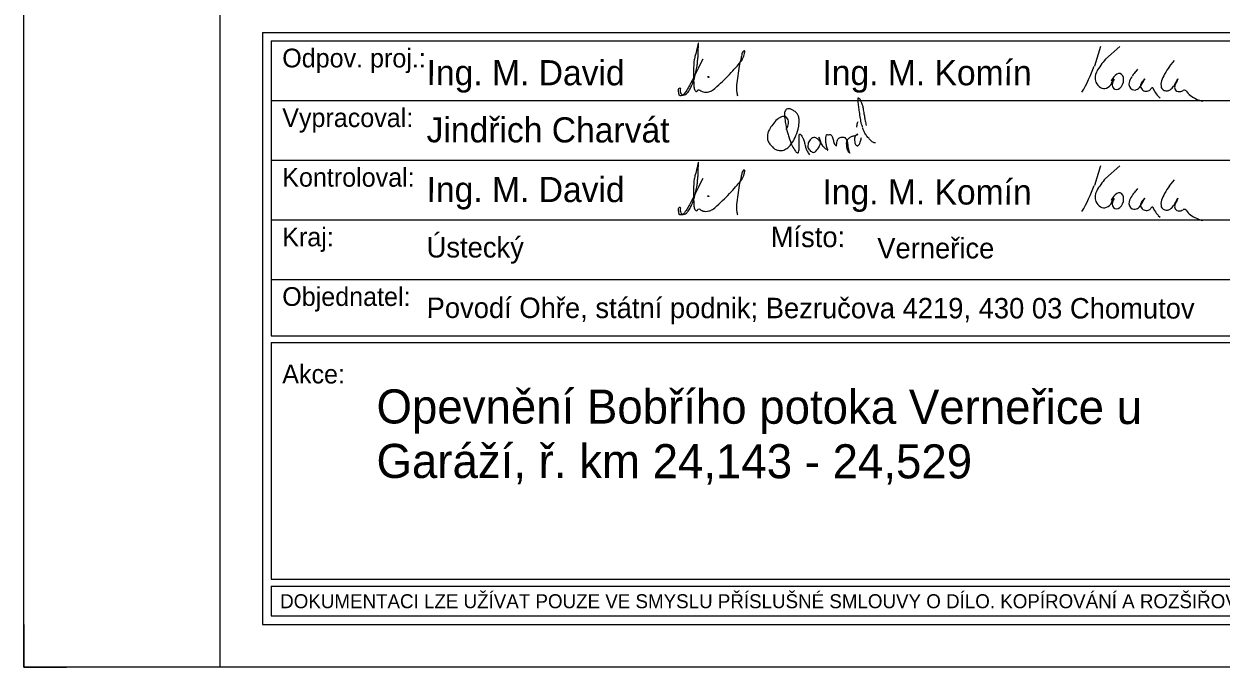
# Model space of a CAD drawing. Extents: x 67.3 to 115.4, y -93.9 to -78.3.
# Drawn here: x 67.26 to 74.28, y -93.93 to -90.16 of the extents above; entities that cross this region are included whole.
import ezdxf

# ---------------------------------------------------------------- set-up
doc = ezdxf.new("R2010")
doc.units = 0
for name, color, linetype in [('07_rozpiska', 7, 'Continuous'), ('07_rámeček', 7, 'Continuous'), ('Default', 7, 'Continuous'), ('Rozpiska + rámeček', 7, 'Continuous')]:
    doc.layers.add(name, color=color, linetype=linetype)

# ---------------------------------------------------------------- blocks, each defined once
blk = doc.blocks.new('Charvat')
at = {"layer": 'Rozpiska + rámeček'}
for points in [[(0.0826, 0.02), (0.0817, 0.0228), (0.0806, 0.0281), (0.0796, 0.0345), (0.0789, 0.0395), (0.0784, 0.0445), (0.0784, 0.0456), (0.0785, 0.0469), (0.0787, 0.0476), (0.0791, 0.0473), (0.0804, 0.0456), (0.0816, 0.0427), (0.0827, 0.0394), (0.0832, 0.0363), (0.0841, 0.0314), (0.0846, 0.0282), (0.0855, 0.0238), (0.086, 0.0216)], [(0.0108, 0.0178), (0.0123, 0.0208), (0.0129, 0.0234), (0.0122, 0.0279), (0.0108, 0.0294), (0.0087, 0.0301), (0.0059, 0.0293), (0.0024, 0.0271), (-0.0017, 0.0225), (-0.0049, 0.0177), (-0.0062, 0.0145), (-0.0067, 0.0115), (-0.0063, 0.0075), (-0.0059, 0.0064), (-0.0039, 0.0034), (-0.0014, 0.0007), (0.001, -0.001), (0.0043, -0.0019), (0.0075, -0.0019), (0.0097, -0.001), (0.0131, 0.0013), (0.0158, 0.0045), (0.0192, 0.0101), (0.022, 0.0182), (0.0223, 0.0193), (0.023, 0.0256), (0.0227, 0.0293), (0.0219, 0.0315), (0.0199, 0.034), (0.017, 0.036), (0.0147, 0.0371), (0.0142, 0.0372), (0.013, 0.0373), (0.0113, 0.0368), (0.0106, 0.0362), (0.0097, 0.0348), (0.0095, 0.0343), (0.0093, 0.0333), (0.0093, 0.0314), (0.0096, 0.0279), (0.0105, 0.0221), (0.012, 0.0151), (0.0133, 0.0108), (0.0166, 0.0023), (0.0195, -0.0026), (0.0202, -0.0035), (0.0214, -0.0042), (0.022, -0.0042), (0.0225, -0.0034), (0.023, -0.0014), (0.0231, 0), (0.0231, 0.0051), (0.0231, 0.0111), (0.0231, 0.0124), (0.0233, 0.0132), (0.0236, 0.0135), (0.024, 0.0133), (0.0254, 0.0115), (0.0268, 0.0092), (0.0279, 0.0059), (0.0289, 0.0018), (0.0298, -0.0012), (0.0315, -0.0041), (0.0327, -0.0059)], [(0.0771, 0.0198), (0.0779, 0.024), (0.0784, 0.0252)], [(0.0428, 0.0062), (0.0417, 0.0075), (0.0401, 0.009), (0.0394, 0.0095), (0.0378, 0.0101), (0.0368, 0.0101), (0.0353, 0.0098), (0.034, 0.0088), (0.0326, 0.0071), (0.0316, 0.0051), (0.0313, 0.0026), (0.0313, 0.0011), (0.0322, -0.0007), (0.0338, -0.0025), (0.0354, -0.0034), (0.0366, -0.0037), (0.0381, -0.0031), (0.0397, -0.0014), (0.0411, 0.0004), (0.0422, 0.0025), (0.043, 0.005), (0.043, 0.0063), (0.0429, 0.0069), (0.0424, 0.0086), (0.0414, 0.0106), (0.0421, 0.009), (0.0433, 0.0053), (0.0444, 0.0034), (0.0458, 0.0017), (0.0476, 0), (0.0497, -0.0015), (0.0498, -0.0016), (0.0499, -0.0016), (0.0499, -0.0014), (0.0492, 0.0003), (0.0487, 0.0022), (0.0482, 0.0055), (0.048, 0.0086), (0.0484, 0.0114), (0.0491, 0.0131), (0.0493, 0.013), (0.0506, 0.0127), (0.0522, 0.0131), (0.0539, 0.0111), (0.0547, 0.0094), (0.0552, 0.0074), (0.0556, 0.0056), (0.0566, 0.0038), (0.058, 0.0025), (0.0582, 0.0031), (0.0585, 0.0057), (0.0589, 0.0076), (0.0593, 0.0083), (0.0604, 0.0095), (0.0616, 0.0102), (0.0632, 0.0106), (0.065, 0.0106), (0.0665, 0.0094), (0.0678, 0.0078), (0.0686, 0.0033), (0.0691, 0.0001), (0.0701, -0.0031), (0.0705, -0.0044), (0.0697, -0.0035), (0.0682, -0.0005), (0.0677, 0.0025), (0.0677, 0.0059), (0.0683, 0.0079), (0.0702, 0.01), (0.0728, 0.0114), (0.0756, 0.0122), (0.0781, 0.0133), (0.0764, 0.0125), (0.0755, 0.0112), (0.0751, 0.0096), (0.0751, 0.0075), (0.0753, 0.005), (0.0753, 0.0048), (0.0758, 0.0038), (0.0766, 0.003), (0.0772, 0.0026), (0.0776, 0.0025), (0.0783, 0.0027), (0.0791, 0.0034), (0.0799, 0.0047), (0.0806, 0.0069), (0.0816, 0.0104)], [(0.0947, 0.0053), (0.0934, 0.0053), (0.0921, 0.0059), (0.0901, 0.0076), (0.0883, 0.0095), (0.0858, 0.0127), (0.0839, 0.0159), (0.0829, 0.0186), (0.0827, 0.0193)]]:
    blk.add_spline(points, degree=3, dxfattribs=at)

msp = doc.modelspace()

# ---------------------------------------------------------------- linework, layer by layer
at = {"layer": '07_rozpiska'}
for points in [[(71.2105, -90.2979), (71.2118, -90.2881), (71.2111, -90.2684), (71.2033, -90.2992), (71.193, -90.3413), (71.1868, -90.3675), (71.1836, -90.4112), (71.182, -90.4469), (71.1852, -90.5214), (71.1884, -90.5411), (71.2011, -90.5528), (71.2056, -90.5496), (71.2066, -90.5473), (71.2137, -90.5424), (71.2263, -90.5489), (71.24, -90.5544), (71.2549, -90.557), (71.273, -90.5541), (71.2934, -90.5457), (71.32, -90.5243), (71.3637, -90.4832), (71.4039, -90.442), (71.4379, -90.4035), (71.4654, -90.3701), (71.4803, -90.3371), (71.4839, -90.3209), (71.4826, -90.3141), (71.4764, -90.3154), (71.4657, -90.3387), (71.4599, -90.3626), (71.4512, -90.4044), (71.4424, -90.4601), (71.4353, -90.5162), (71.4346, -90.545), (71.4382, -90.5667), (71.4401, -90.5774)], [(71.2043, -90.4031), (71.2063, -90.3772), (71.2088, -90.3546), (71.2108, -90.3303), (71.2105, -90.2979)], [(71.2367, -90.3636), (71.2092, -90.4184), (71.1629, -90.5104), (71.1295, -90.5648), (71.1172, -90.5761), (71.1078, -90.5777), (71.102, -90.5771), (71.0977, -90.5703), (71.0958, -90.5583)], [(71.0958, -90.5583), (71.0939, -90.5466), (71.0948, -90.5389), (71.0997, -90.5324), (71.1033, -90.5317), (71.1052, -90.5437), (71.1058, -90.558), (71.1139, -90.5703), (71.1253, -90.5745), (71.136, -90.5706), (71.1454, -90.5628), (71.1505, -90.556), (71.1658, -90.5317), (71.1719, -90.5201), (71.1878, -90.4738), (71.2043, -90.4031)], [(71.2691, -90.4653), (71.2668, -90.4663), (71.2668, -90.4683), (71.2685, -90.4692), (71.2717, -90.4699), (71.2723, -90.4683), (71.2723, -90.4666), (71.2691, -90.4653)], [(71.2105, -90.9979), (71.2118, -90.9881), (71.2111, -90.9684), (71.2033, -90.9992), (71.193, -91.0413), (71.1868, -91.0675), (71.1836, -91.1112), (71.182, -91.1469), (71.1852, -91.2214), (71.1884, -91.2411), (71.2011, -91.2528), (71.2056, -91.2496), (71.2066, -91.2473), (71.2137, -91.2424), (71.2263, -91.2489), (71.24, -91.2544), (71.2549, -91.257), (71.273, -91.2541), (71.2934, -91.2457), (71.32, -91.2243), (71.3637, -91.1832), (71.4039, -91.142), (71.4379, -91.1035), (71.4654, -91.0701), (71.4803, -91.0371), (71.4839, -91.0209), (71.4826, -91.0141), (71.4764, -91.0154), (71.4657, -91.0387), (71.4599, -91.0626), (71.4512, -91.1044), (71.4424, -91.1601), (71.4353, -91.2162), (71.4346, -91.245), (71.4382, -91.2667), (71.4401, -91.2774)], [(71.2043, -91.1031), (71.2063, -91.0772), (71.2088, -91.0546), (71.2108, -91.0303), (71.2105, -90.9979)], [(71.2367, -91.0636), (71.2092, -91.1184), (71.1629, -91.2104), (71.1295, -91.2648), (71.1172, -91.2761), (71.1078, -91.2777), (71.102, -91.2771), (71.0977, -91.2703), (71.0958, -91.2583)], [(71.0958, -91.2583), (71.0939, -91.2466), (71.0948, -91.2389), (71.0997, -91.2324), (71.1033, -91.2317), (71.1052, -91.2437), (71.1058, -91.258), (71.1139, -91.2703), (71.1253, -91.2745), (71.136, -91.2706), (71.1454, -91.2628), (71.1505, -91.256), (71.1658, -91.2317), (71.1719, -91.2201), (71.1878, -91.1738), (71.2043, -91.1031)], [(71.2691, -91.1653), (71.2668, -91.1663), (71.2668, -91.1683), (71.2685, -91.1692), (71.2717, -91.1699), (71.2723, -91.1683), (71.2723, -91.1666), (71.2691, -91.1653)]]:
    msp.add_spline(points, degree=3, dxfattribs=at)
at = {"layer": 'Default'}
for p, q in [((73.6352, -90.5049), (73.6496, -90.479)), ((73.8771, -90.5337), (73.8872, -90.551)), ((73.9088, -90.5798), (73.9203, -90.5913)), ((73.6352, -91.2049), (73.6496, -91.179)), ((73.8771, -91.2337), (73.8872, -91.251)), ((73.9088, -91.2798), (73.9203, -91.2913))]:
    msp.add_line(p, q, dxfattribs=at)
for points in [[(73.5704, -90.2889), (73.5344, -90.4041)], [(73.6827, -90.2889), (73.5992, -90.3638)], [(73.7864, -90.4214), (73.7763, -90.4358)], [(74.0024, -90.371), (73.9736, -90.407)], [(73.7576, -90.4617), (73.7547, -90.4646)], [(73.808, -90.5049), (73.808, -90.5078)], [(73.8224, -90.4905), (73.8296, -90.479), (73.8195, -90.4905)], [(73.9995, -90.5222), (74.024, -90.479), (74.0139, -90.5049)], [(73.8051, -90.5222), (73.8051, -90.5222)], [(73.5704, -90.9889), (73.5344, -91.1041)], [(73.6827, -90.9889), (73.5992, -91.0638)], [(74.0024, -91.071), (73.9736, -91.107)], [(73.7864, -91.1214), (73.7763, -91.1358)], [(73.7576, -91.1617), (73.7547, -91.1646)], [(73.808, -91.2049), (73.808, -91.2078)], [(73.8224, -91.1905), (73.8296, -91.179), (73.8195, -91.1905)], [(73.9995, -91.2222), (74.024, -91.179), (74.0139, -91.2049)], [(73.8051, -91.2222), (73.8051, -91.2222)]]:
    msp.add_lwpolyline(points, dxfattribs=at)
for centre, radius, start, end in [((73.8592, -90.6056), 0.3545, 137.00062, 151.51062), ((72.6011, -90.0574), 0.9948, 329.80858, 339.56815), ((73.6116, -90.4722), 0.0732, 150.83631, 201.23374), ((73.9981, -90.6186), 0.288, 140.57196, 146.46893), ((74.2053, -90.5927), 0.2956, 141.11668, 151.43002), ((73.6181, -90.4626), 0.083, 205.78195, 234.22418), ((73.5672, -90.4548), 0.0864, 295.93387, 323.63221), ((73.7124, -90.5204), 0.084, 133.12102, 160.6603), ((73.6916, -90.5127), 0.0529, 142.82783, 193.29225), ((73.8433, -90.5272), 0.1085, 146.31446, 165.71836), ((73.5134, -90.3072), 0.288, 326.31446, 326.46946), ((73.6545, -90.4115), 0.1862, 320.58833, 335.16259), ((73.8338, -90.5192), 0.0288, 154.94151, 187.17365), ((73.861, -90.529), 0.0576, 139.19606, 154.94016), ((73.9862, -90.5134), 0.0617, 158.78845, 195.14726), ((74.127, -90.5521), 0.2075, 150.931, 162.8917), ((74.0714, -90.5367), 0.0677, 151.17648, 169.00349), ((73.5897, -90.499), 0.0369, 236.98468, 294.62862), ((73.6296, -90.6162), 0.0864, 108.04736, 108.08265), ((73.77, -90.5122), 0.0323, 245.35778, 276.92267), ((73.763, -90.4981), 0.0475, 283.31943, 318.16716), ((73.8338, -90.5205), 0.0286, 186.45097, 212.31824), ((73.8371, -90.5186), 0.0324, 212.08411, 258.70933), ((73.8387, -90.515), 0.0362, 257.35338, 296.27075), ((73.8324, -90.5108), 0.043, 301.37529, 327.02531), ((73.8734, -90.5371), 0.00576, 26.63136, 150.41952), ((73.9647, -90.5135), 0.0864, 206.63144, 229.82938), ((73.9519, -90.5215), 0.0265, 197.61582, 249.38851), ((73.9583, -90.5028), 0.0463, 250.12564, 275.82035), ((73.959, -90.514), 0.035, 276.59581, 304.89281), ((73.9172, -90.4655), 0.099, 308.6573, 325.5075), ((74.0344, -90.5279), 0.0297, 172.16185, 218.17447), ((74.0335, -90.5195), 0.0349, 229.93747, 256.22885), ((74.0297, -90.5079), 0.0458, 264.36538, 302.31991), ((74.0613, -90.5581), 0.0136, 38.96313, 121.674), ((74.1807, -90.4734), 0.1329, 214.99845, 231.36881), ((74.2172, -90.4078), 0.2073, 234.79421, 256.99308), ((73.8592, -91.3056), 0.3545, 137.00062, 151.51062), ((72.6011, -90.7574), 0.9948, 329.80858, 339.56815), ((73.6116, -91.1722), 0.0732, 150.83631, 201.23374), ((73.9981, -91.3186), 0.288, 140.57196, 146.46893), ((74.2053, -91.2927), 0.2956, 141.11668, 151.43002), ((73.6181, -91.1626), 0.083, 205.78195, 234.22418), ((73.5672, -91.1548), 0.0864, 295.93387, 323.63221), ((73.7124, -91.2204), 0.084, 133.12102, 160.6603), ((73.6916, -91.2127), 0.0529, 142.82783, 193.29225), ((73.8433, -91.2272), 0.1085, 146.31446, 165.71836), ((73.5134, -91.0072), 0.288, 326.31446, 326.46946), ((73.6545, -91.1115), 0.1862, 320.58833, 335.16259), ((73.8338, -91.2192), 0.0288, 154.94151, 187.17365), ((73.861, -91.229), 0.0576, 139.19606, 154.94016), ((73.9862, -91.2134), 0.0617, 158.78845, 195.14726), ((74.127, -91.2521), 0.2075, 150.931, 162.8917), ((74.0714, -91.2367), 0.0677, 151.17648, 169.00349), ((73.5897, -91.199), 0.0369, 236.98468, 294.62862), ((73.6296, -91.3162), 0.0864, 108.04736, 108.08265), ((73.77, -91.2122), 0.0323, 245.35778, 276.92267), ((73.763, -91.1981), 0.0475, 283.31943, 318.16716), ((73.8338, -91.2205), 0.0286, 186.45097, 212.31824), ((73.8371, -91.2186), 0.0324, 212.08411, 258.70933), ((73.8387, -91.215), 0.0362, 257.35338, 296.27075), ((73.8324, -91.2108), 0.043, 301.37529, 327.02531), ((73.8734, -91.2371), 0.00576, 26.63136, 150.41952), ((73.9647, -91.2135), 0.0864, 206.63144, 229.82938), ((73.9519, -91.2215), 0.0265, 197.61582, 249.38851), ((73.9583, -91.2028), 0.0463, 250.12564, 275.82035), ((73.959, -91.214), 0.035, 276.59581, 304.89281), ((73.9172, -91.1655), 0.099, 308.6573, 325.5075), ((74.0344, -91.2279), 0.0297, 172.16185, 218.17447), ((74.0335, -91.2195), 0.0349, 229.93747, 256.22885), ((74.0297, -91.2079), 0.0458, 264.36538, 302.31991), ((74.0613, -91.2581), 0.0136, 38.96313, 121.674), ((74.1807, -91.1734), 0.1329, 214.99845, 231.36881), ((74.2172, -91.1078), 0.2073, 234.79421, 256.99308)]:
    msp.add_arc(centre, radius, start, end, dxfattribs=at)
for centre, major_axis, ratio, start_param, end_param in [((73.6711, -90.4946), (0.0152, 0.0459), 0.677007, 2.488228, 7.220838), ((73.7739, -90.5113), (-0.0357, 0.0109), 0.932374, 0, 1.363098), ((73.6711, -91.1946), (0.0152, 0.0459), 0.677007, 2.488228, 7.220838), ((73.7739, -91.2113), (-0.0357, 0.0109), 0.932374, 0, 1.363098)]:
    msp.add_ellipse(centre, major_axis=major_axis, ratio=ratio, start_param=start_param, end_param=end_param, dxfattribs=at)
at = {"layer": 'Rozpiska + rámeček'}
for p, q in [((68.6554, -90.2063), (68.6554, -93.6813)), ((68.6554, -90.2063), (77.2554, -90.2063)), ((68.7054, -90.2563), (68.7054, -91.9863)), ((68.7054, -90.2563), (74.3654, -90.2563)), ((68.7054, -90.6063), (74.3654, -90.6063)), ((68.7054, -90.9563), (74.3654, -90.9563)), ((68.7054, -91.3063), (74.3654, -91.3063)), ((68.7054, -91.6563), (74.3654, -91.6563)), ((68.7054, -91.9863), (74.3654, -91.9863)), ((68.7054, -92.0263), (74.3654, -92.0263)), ((68.7054, -92.0263), (68.7054, -93.4163)), ((68.7054, -93.4163), (74.3654, -93.4163)), ((68.7054, -93.4563), (77.2054, -93.4563)), ((68.7054, -93.4563), (68.7054, -93.6313)), ((68.7054, -93.6313), (77.2054, -93.6313)), ((68.6554, -93.6813), (77.2554, -93.6813))]:
    msp.add_line(p, q, dxfattribs=at)
for points in [[(67.2554, -79.0813), (77.7554, -79.0813), (77.7554, -93.9313), (67.2554, -93.9313)], [(68.4054, -86.5063), (77.5054, -86.5063), (77.5054, -93.9313), (68.4054, -93.9313)]]:
    msp.add_lwpolyline(points, close=True, dxfattribs=at)
msp.add_lwpolyline([(67.2554, -93.6813), (67.2554, -93.9313), (67.5054, -93.9313)], dxfattribs=at)

# ---------------------------------------------------------------- block references
at = {"layer": '07_rámeček', "xscale": 6.250000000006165, "yscale": 6.250000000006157, "rotation": 3.739011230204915e-09}
msp.add_blockref('Charvat', (71.6584, -90.887), dxfattribs=at)

# ---------------------------------------------------------------- texts
at = {"layer": '07_rozpiska'}
for s, p in [('Opevnění Bobřího potoka Verneřice u ', (69.3234, -92.5013)), ('Garáží, ř. km 24,143 - 24,529', (69.3232, -92.8213))]:
    msp.add_text(s, height=0.2, rotation=359.95393, dxfattribs=at).set_placement(p)
at = {"layer": 'Rozpiska + rámeček'}
for s, height, rotation, p in [('Odpov. proj.:', 0.11, 359.95393, (68.7704, -90.4113)), ('Ing. M. David', 0.147465, 359.95278, (69.6171, -90.5157)), ('Ing. M. Komín', 0.147465, 359.95278, (71.9388, -90.5157)), ('Vypracoval:', 0.11, 359.95393, (68.7704, -90.7613)), ('Jindřich Charvát', 0.147465, 359.95278, (69.6171, -90.8513)), ('Kontroloval:', 0.11, 359.95393, (68.7704, -91.1113)), ('Ing. M. David', 0.147465, 359.95278, (69.6171, -91.2013)), ('Ing. M. Komín', 0.147465, 359.95278, (71.9388, -91.2157)), ('Kraj:', 0.11, 359.95393, (68.7704, -91.4613)), ('Místo:', 0.12, 359.95393, (71.6354, -91.4663)), ('Ústecký', 0.12, 359.95393, (69.6171, -91.5273)), ('Verneřice', 0.12, 359.95278, (72.2604, -91.5321)), ('Objednatel:', 0.11, 359.95393, (68.7704, -91.8113)), ('Povodí Ohře, státní podnik; Bezručova 4219, 430 03 Chomutov', 0.12, 359.95278, (69.6171, -91.8821)), ('Akce:', 0.11, 359.95393, (68.7704, -92.2663))]:
    msp.add_text(s, height=height, rotation=rotation, dxfattribs=at).set_placement(p)
msp.add_text('DOKUMENTACI LZE UŽÍVAT POUZE VE SMYSLU PŘÍSLUŠNÉ SMLOUVY O DÍLO. KOPÍROVÁNÍ A ROZŠIŘOVÁNÍ POUZE PO PŘEDCHOZÍM SOUHLASU  AZ CONSULT spol. s. r.o.', height=0.0822563, dxfattribs=at).set_placement((68.7584, -93.5859))

doc.saveas('drawing.dxf')
